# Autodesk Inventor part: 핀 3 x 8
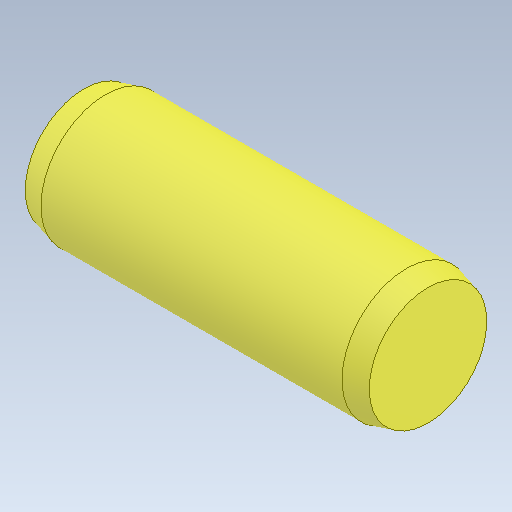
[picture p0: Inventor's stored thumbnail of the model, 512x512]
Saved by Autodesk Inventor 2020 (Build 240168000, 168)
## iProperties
Created: 2024-04
Part Number: 핀 3 x 8
Material: 강철, 연강
Description: 평행 핀
Document SubType Name: Modeling
Designer: oem
Density: 7.85 g/cm^3
Appearance: 기본값
Mass: 0.439099 g
Surface Area: 0.870195 cm^2
Volume: 0.0559361 cm^3
Sending System: Autodesk Inventor 2025
Preprocessor: ST-DEVELOPER v20
Author: jhkim
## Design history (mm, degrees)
feature "Solid1"
node "솔리드1"
